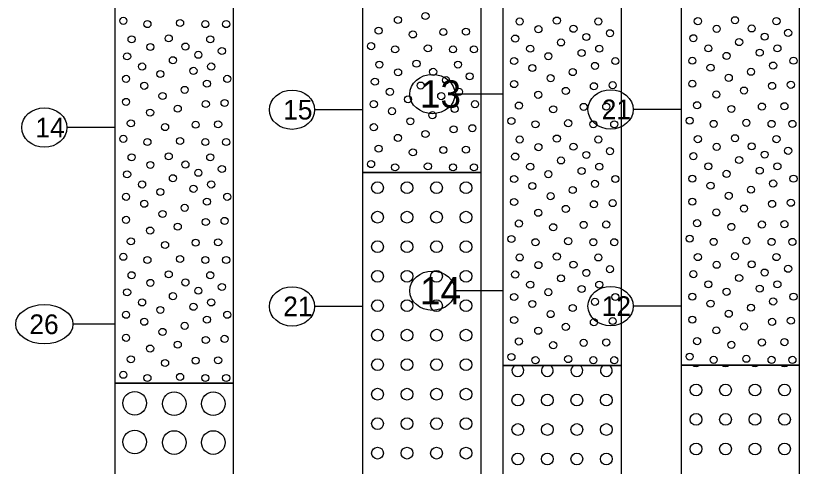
# Model space of a CAD drawing. Extents: x 2345490 to 2436403, y 465165 to 573888.
# Drawn here: x 2389895.3 to 2390094.5, y 557571.2 to 557685.8 of the extents above; entities that cross this region are included whole.
import ezdxf

# ---------------------------------------------------------------- set-up
doc = ezdxf.new("R2010")
doc.units = 0
for name, color, linetype in [('Prop Road Sect_ Boring - Material (Outline)', 7, 'Continuous'), ('Prop Road Sect_ Boring - Peripheral (SPT Oval + Leader)', 7, 'Continuous'), ('Prop Road Sect_ Boring - Peripheral (SPT Tx)', 7, 'Continuous')]:
    doc.layers.add(name, color=color, linetype=linetype)

msp = doc.modelspace()

# ---------------------------------------------------------------- linework, layer by layer
at = {"layer": 'Prop Road Sect_ Boring - Material (Outline)'}
for points in [[(2389983.5425, 557845.85303), (2390013.5425, 557845.85303), (2390013.5425, 557645.85303), (2389983.5425, 557645.85303)], [(2389920.5425, 557842.314), (2389950.5425, 557842.314), (2389950.5425, 557592.314), (2389920.5425, 557592.314)], [(2390019.2285, 557796.83938), (2390049.2285, 557796.83938), (2390049.2285, 557596.83938), (2390019.2285, 557596.83938)], [(2390064.5425, 557696.92666), (2390094.5425, 557696.92666), (2390094.5425, 557596.92666), (2390064.5425, 557596.92666)], [(2389983.5425, 557645.85303), (2390013.5425, 557645.85303), (2390013.5425, 557495.85303), (2389983.5425, 557495.85303)], [(2390019.2285, 557596.83938), (2390049.2285, 557596.83938), (2390049.2285, 557546.83938), (2390019.2285, 557546.83938)], [(2390064.5425, 557596.92666), (2390094.5425, 557596.92666), (2390094.5425, 557496.92666), (2390064.5425, 557496.92666)], [(2389920.5425, 557592.314), (2389950.5425, 557592.314), (2389950.5425, 557492.314), (2389920.5425, 557492.314)]]:
    msp.add_lwpolyline(points, close=True, dxfattribs=at)
for centre, radius in [((2389999.47557, 557685.65437), 0.9), ((2389922.64554, 557684.43532), 0.9), ((2389928.76556, 557683.61032), 0.9), ((2389937.07557, 557683.88032), 0.9), ((2389943.48059, 557683.61032), 0.9), ((2389948.7906, 557683.61032), 0.9), ((2389992.45556, 557684.66437), 0.9), ((2390023.42542, 557684.27036), 0.9), ((2390032.87723, 557684.50221), 0.9), ((2390043.42155, 557684.27036), 0.9), ((2390068.73942, 557684.35764), 0.9), ((2390078.19123, 557684.5895), 0.9), ((2390088.73555, 557684.35764), 0.9), ((2389987.55055, 557681.93436), 0.9), ((2389996.26557, 557680.98936), 0.9), ((2390004.02058, 557681.58936), 0.9), ((2390009.75059, 557681.67936), 0.9), ((2390028.20437, 557682.32105), 0.9), ((2390037.11379, 557682.42714), 0.9), ((2390046.38159, 557681.29574), 0.9), ((2390073.51837, 557682.40833), 0.9), ((2390082.42779, 557682.51443), 0.9), ((2390091.69559, 557681.38303), 0.9), ((2389924.73942, 557679.74498), 0.9), ((2389934.19123, 557679.97684), 0.9), ((2389944.73555, 557679.74498), 0.9), ((2390022.29155, 557679.93074), 0.9), ((2390033.92653, 557678.94902), 0.9), ((2390040.39658, 557680.33574), 0.9), ((2390067.60555, 557680.01803), 0.9), ((2390079.24053, 557679.03631), 0.9), ((2390085.71058, 557680.42303), 0.9), ((2389929.51837, 557677.79567), 0.9), ((2389938.42779, 557677.90177), 0.9), ((2389985.64554, 557678.00435), 0.9), ((2389991.76556, 557677.17935), 0.9), ((2390000.07557, 557677.44935), 0.9), ((2390006.48059, 557677.17935), 0.9), ((2390011.7906, 557677.17935), 0.9), ((2390026.10155, 557677.35074), 0.9), ((2390043.66659, 557677.35074), 0.9), ((2390071.41555, 557677.43802), 0.9), ((2390088.98059, 557677.43802), 0.9), ((2389923.60555, 557675.40537), 0.9), ((2389941.71058, 557675.81037), 0.9), ((2389947.69559, 557676.77037), 0.9), ((2390030.72156, 557675.44573), 0.9), ((2390039.16658, 557676.25573), 0.9), ((2390076.03556, 557675.53302), 0.9), ((2390084.48058, 557676.34302), 0.9), ((2389935.24053, 557674.42365), 0.9), ((2389987.73942, 557673.31401), 0.9), ((2389997.19123, 557673.54587), 0.9), ((2390007.73555, 557673.31401), 0.9), ((2390022.02155, 557674.21573), 0.9), ((2390042.57159, 557672.98573), 0.9), ((2390047.7466, 557674.21573), 0.9), ((2390067.33555, 557674.30301), 0.9), ((2390087.88559, 557673.07301), 0.9), ((2390093.0606, 557674.30301), 0.9), ((2389927.41555, 557672.82536), 0.9), ((2389932.03556, 557670.92036), 0.9), ((2389940.48058, 557671.73036), 0.9), ((2389944.98059, 557672.82536), 0.9), ((2389992.51837, 557671.3647), 0.9), ((2390001.42779, 557671.4708), 0.9), ((2390026.64156, 557672.44573), 0.9), ((2390036.93158, 557671.41072), 0.9), ((2390071.95556, 557672.53301), 0.9), ((2390082.24558, 557671.49801), 0.9), ((2389923.33555, 557669.69035), 0.9), ((2389949.0606, 557669.69035), 0.9), ((2389986.60555, 557668.9744), 0.9), ((2390004.71058, 557669.3794), 0.9), ((2390010.69559, 557670.3394), 0.9), ((2390031.29156, 557669.86572), 0.9), ((2390076.60556, 557669.95301), 0.9), ((2389927.95556, 557667.92035), 0.9), ((2389943.88559, 557668.46035), 0.9), ((2389998.24053, 557667.99268), 0.9), ((2390022.02155, 557668.36572), 0.9), ((2390042.30159, 557667.81072), 0.9), ((2390047.0716, 557668.09572), 0.9), ((2390067.33555, 557668.453), 0.9), ((2390087.61559, 557667.898), 0.9), ((2390092.3856, 557668.183), 0.9), ((2389932.60556, 557665.34035), 0.9), ((2389938.24558, 557666.88535), 0.9), ((2389990.41555, 557666.39439), 0.9), ((2390003.48058, 557665.29939), 0.9), ((2390007.98059, 557666.39439), 0.9), ((2390028.14156, 557665.63571), 0.9), ((2390035.16157, 557666.62571), 0.9), ((2390073.45556, 557665.723), 0.9), ((2390080.47557, 557666.713), 0.9), ((2389923.33555, 557663.84034), 0.9), ((2389943.61559, 557663.28534), 0.9), ((2389948.3856, 557663.57034), 0.9), ((2389986.33555, 557663.25938), 0.9), ((2389995.03556, 557664.48939), 0.9), ((2390012.0606, 557663.25938), 0.9), ((2390068.55055, 557662.99299), 0.9), ((2389929.45556, 557661.11034), 0.9), ((2389936.47557, 557662.10034), 0.9), ((2389990.95556, 557661.48938), 0.9), ((2390006.88559, 557662.02938), 0.9), ((2390023.23655, 557662.90571), 0.9), ((2390031.95157, 557661.9607), 0.9), ((2390039.70658, 557662.56071), 0.9), ((2390045.43659, 557662.65071), 0.9), ((2390077.26557, 557662.04799), 0.9), ((2390085.02058, 557662.64799), 0.9), ((2390090.75059, 557662.73799), 0.9), ((2390001.24558, 557660.45438), 0.9), ((2390021.33154, 557658.9757), 0.9), ((2390066.64554, 557659.06298), 0.9), ((2389924.55055, 557658.38033), 0.9), ((2389933.26557, 557657.43533), 0.9), ((2389941.02058, 557658.03533), 0.9), ((2389946.75059, 557658.12533), 0.9), ((2389986.33555, 557657.40937), 0.9), ((2389995.60556, 557658.90938), 0.9), ((2390011.3856, 557657.13937), 0.9), ((2390027.45156, 557658.1507), 0.9), ((2390035.76157, 557658.4207), 0.9), ((2390042.16659, 557658.1507), 0.9), ((2390047.4766, 557658.1507), 0.9), ((2390072.76556, 557658.23798), 0.9), ((2390081.07557, 557658.50798), 0.9), ((2390087.48059, 557658.23798), 0.9), ((2390092.7906, 557658.23798), 0.9), ((2389999.47557, 557655.66937), 0.9), ((2390006.61559, 557656.85437), 0.9), ((2389922.64554, 557654.45032), 0.9), ((2389928.76556, 557653.62532), 0.9), ((2389937.07557, 557653.89532), 0.9), ((2389943.48059, 557653.62532), 0.9), ((2389948.7906, 557653.62532), 0.9), ((2389992.45556, 557654.67937), 0.9), ((2390023.42542, 557654.28536), 0.9), ((2390032.87723, 557654.51721), 0.9), ((2390043.42155, 557654.28536), 0.9), ((2390068.73942, 557654.37264), 0.9), ((2390078.19123, 557654.6045), 0.9), ((2390088.73555, 557654.37264), 0.9), ((2389987.55055, 557651.94936), 0.9), ((2389996.26557, 557651.00436), 0.9), ((2390004.02058, 557651.60436), 0.9), ((2390009.75059, 557651.69436), 0.9), ((2390028.20437, 557652.33605), 0.9), ((2390037.11379, 557652.44214), 0.9), ((2390046.38159, 557651.31074), 0.9), ((2390073.51837, 557652.42333), 0.9), ((2390082.42779, 557652.52943), 0.9), ((2390091.69559, 557651.39803), 0.9), ((2389924.73942, 557649.75998), 0.9), ((2389934.19123, 557649.99184), 0.9), ((2389944.73555, 557649.75998), 0.9), ((2390022.29155, 557649.94574), 0.9), ((2390040.39658, 557650.35074), 0.9), ((2390067.60555, 557650.03303), 0.9), ((2390079.24053, 557649.05131), 0.9), ((2390085.71058, 557650.43803), 0.9), ((2389929.51837, 557647.81067), 0.9), ((2389938.42779, 557647.91677), 0.9), ((2389985.64554, 557648.01935), 0.9), ((2389991.76556, 557647.19435), 0.9), ((2390000.07557, 557647.46435), 0.9), ((2390006.48059, 557647.19435), 0.9), ((2390011.7906, 557647.19435), 0.9), ((2390026.10155, 557647.36574), 0.9), ((2390033.92653, 557648.96402), 0.9), ((2390043.66659, 557647.36574), 0.9), ((2390071.41555, 557647.45302), 0.9), ((2390088.98059, 557647.45302), 0.9), ((2389923.60555, 557645.42037), 0.9), ((2389941.71058, 557645.82537), 0.9), ((2389947.69559, 557646.78537), 0.9), ((2390030.72156, 557645.46073), 0.9), ((2390039.16658, 557646.27073), 0.9), ((2390076.03556, 557645.54802), 0.9), ((2390084.48058, 557646.35802), 0.9), ((2389935.24053, 557644.43865), 0.9), ((2390022.02155, 557644.23073), 0.9), ((2390047.7466, 557644.23073), 0.9), ((2390067.33555, 557644.31801), 0.9), ((2390087.88559, 557643.08801), 0.9), ((2390093.0606, 557644.31801), 0.9), ((2389927.41555, 557642.84036), 0.9), ((2389940.48058, 557641.74536), 0.9), ((2389944.98059, 557642.84036), 0.9), ((2389987.27939, 557642.0197), 1.5), ((2389994.77939, 557642.0197), 1.5), ((2390002.27939, 557642.0197), 1.5), ((2390009.77939, 557642.0197), 1.5), ((2390026.64156, 557642.46073), 0.9), ((2390036.93158, 557641.42572), 0.9), ((2390042.57159, 557643.00073), 0.9), ((2390071.95556, 557642.54801), 0.9), ((2390082.24558, 557641.51301), 0.9), ((2389923.33555, 557639.70535), 0.9), ((2389932.03556, 557640.93536), 0.9), ((2389949.0606, 557639.70535), 0.9), ((2390031.29156, 557639.88072), 0.9), ((2390076.60556, 557639.96801), 0.9), ((2389927.95556, 557637.93535), 0.9), ((2389943.88559, 557638.47535), 0.9), ((2390022.02155, 557638.38072), 0.9), ((2390042.30159, 557637.82572), 0.9), ((2390047.0716, 557638.11072), 0.9), ((2390067.33555, 557638.468), 0.9), ((2390087.61559, 557637.913), 0.9), ((2390092.3856, 557638.198), 0.9), ((2389932.60556, 557635.35535), 0.9), ((2389938.24558, 557636.90035), 0.9), ((2389987.27939, 557634.5197), 1.5), ((2389994.77939, 557634.5197), 1.5), ((2390002.27939, 557634.5197), 1.5), ((2390009.77939, 557634.5197), 1.5), ((2390028.14156, 557635.65071), 0.9), ((2390035.16157, 557636.64071), 0.9), ((2390073.45556, 557635.738), 0.9), ((2390080.47557, 557636.728), 0.9), ((2389923.33555, 557633.85534), 0.9), ((2389943.61559, 557633.30034), 0.9), ((2389948.3856, 557633.58534), 0.9), ((2389929.45556, 557631.12534), 0.9), ((2389936.47557, 557632.11534), 0.9), ((2390023.23655, 557632.92071), 0.9), ((2390031.95157, 557631.9757), 0.9), ((2390039.70658, 557632.57571), 0.9), ((2390045.43659, 557632.66571), 0.9), ((2390068.55055, 557633.00799), 0.9), ((2390077.26557, 557632.06299), 0.9), ((2390085.02058, 557632.66299), 0.9), ((2390090.75059, 557632.75299), 0.9), ((2390066.64554, 557629.07798), 0.9), ((2389924.55055, 557628.39533), 0.9), ((2389933.26557, 557627.45033), 0.9), ((2389941.02058, 557628.05033), 0.9), ((2389946.75059, 557628.14033), 0.9), ((2389987.27939, 557627.0197), 1.5), ((2389994.77939, 557627.0197), 1.5), ((2390002.27939, 557627.0197), 1.5), ((2390009.77939, 557627.0197), 1.5), ((2390021.33154, 557628.9907), 0.9), ((2390027.45156, 557628.1657), 0.9), ((2390035.76157, 557628.4357), 0.9), ((2390042.16659, 557628.1657), 0.9), ((2390047.4766, 557628.1657), 0.9), ((2390072.76556, 557628.25298), 0.9), ((2390081.07557, 557628.52298), 0.9), ((2390087.48059, 557628.25298), 0.9), ((2390092.7906, 557628.25298), 0.9), ((2389922.64554, 557624.46532), 0.9), ((2389928.76556, 557623.64032), 0.9), ((2389937.07557, 557623.91032), 0.9), ((2389943.48059, 557623.64032), 0.9), ((2389948.7906, 557623.64032), 0.9), ((2390023.42542, 557624.30036), 0.9), ((2390032.87723, 557624.53221), 0.9), ((2390043.42155, 557624.30036), 0.9), ((2390068.73942, 557624.38764), 0.9), ((2390078.19123, 557624.6195), 0.9), ((2390088.73555, 557624.38764), 0.9), ((2390028.20437, 557622.35105), 0.9), ((2390037.11379, 557622.45714), 0.9), ((2390046.38159, 557621.32574), 0.9), ((2390073.51837, 557622.43833), 0.9), ((2390082.42779, 557622.54443), 0.9), ((2390091.69559, 557621.41303), 0.9), ((2389924.73942, 557619.77498), 0.9), ((2389934.19123, 557620.00684), 0.9), ((2389944.73555, 557619.77498), 0.9), ((2389987.27939, 557619.5197), 1.5), ((2389994.77939, 557619.5197), 1.5), ((2390002.27939, 557619.5197), 1.5), ((2390009.77939, 557619.5197), 1.5), ((2390022.29155, 557619.96074), 0.9), ((2390040.39658, 557620.36574), 0.9), ((2390067.60555, 557620.04803), 0.9), ((2390085.71058, 557620.45303), 0.9), ((2389929.51837, 557617.82567), 0.9), ((2389938.42779, 557617.93177), 0.9), ((2390026.10155, 557617.38074), 0.9), ((2390033.92653, 557618.97902), 0.9), ((2390043.66659, 557617.38074), 0.9), ((2390071.41555, 557617.46802), 0.9), ((2390079.24053, 557619.06631), 0.9), ((2390088.98059, 557617.46802), 0.9), ((2389923.60555, 557615.43537), 0.9), ((2389941.71058, 557615.84037), 0.9), ((2389947.69559, 557616.80037), 0.9), ((2390030.72156, 557615.47573), 0.9), ((2390039.16658, 557616.28573), 0.9), ((2390076.03556, 557615.56302), 0.9), ((2390084.48058, 557616.37302), 0.9), ((2389935.24053, 557614.45365), 0.9), ((2390022.02155, 557614.24573), 0.9), ((2390047.7466, 557614.24573), 0.9), ((2390067.33555, 557614.33301), 0.9), ((2390093.0606, 557614.33301), 0.9), ((2389927.41555, 557612.85536), 0.9), ((2389940.48058, 557611.76036), 0.9), ((2389944.98059, 557612.85536), 0.9), ((2389987.27939, 557612.0347), 1.5), ((2389994.77939, 557612.0347), 1.5), ((2390002.27939, 557612.0347), 1.5), ((2390009.77939, 557612.0347), 1.5), ((2390026.64156, 557612.47573), 0.9), ((2390036.93158, 557611.44072), 0.9), ((2390042.57159, 557613.01573), 0.9), ((2390071.95556, 557612.56301), 0.9), ((2390082.24558, 557611.52801), 0.9), ((2390087.88559, 557613.10301), 0.9), ((2389923.33555, 557609.72035), 0.9), ((2389932.03556, 557610.95036), 0.9), ((2389949.0606, 557609.72035), 0.9), ((2390031.29156, 557609.89572), 0.9), ((2390076.60556, 557609.98301), 0.9), ((2389927.95556, 557607.95035), 0.9), ((2389943.88559, 557608.49035), 0.9), ((2390022.02155, 557608.39572), 0.9), ((2390042.30159, 557607.84072), 0.9), ((2390047.0716, 557608.12572), 0.9), ((2390067.33555, 557608.483), 0.9), ((2390087.61559, 557607.928), 0.9), ((2390092.3856, 557608.213), 0.9), ((2389932.60556, 557605.37035), 0.9), ((2389938.24558, 557606.91535), 0.9), ((2390028.14156, 557605.66571), 0.9), ((2390035.16157, 557606.65571), 0.9), ((2390073.45556, 557605.753), 0.9), ((2390080.47557, 557606.743), 0.9), ((2389923.33555, 557603.87034), 0.9), ((2389943.61559, 557603.31534), 0.9), ((2389948.3856, 557603.60034), 0.9), ((2389987.27939, 557604.5347), 1.5), ((2389994.77939, 557604.5347), 1.5), ((2390002.27939, 557604.5347), 1.5), ((2390009.77939, 557604.5347), 1.5), ((2389936.47557, 557602.13034), 0.9), ((2390023.23655, 557602.93571), 0.9), ((2390031.95157, 557601.9907), 0.9), ((2390039.70658, 557602.59071), 0.9), ((2390045.43659, 557602.68071), 0.9), ((2390068.55055, 557603.02299), 0.9), ((2390077.26557, 557602.07799), 0.9), ((2390085.02058, 557602.67799), 0.9), ((2390090.75059, 557602.76799), 0.9), ((2389929.45556, 557601.14034), 0.9), ((2389924.55055, 557598.41033), 0.9), ((2389933.26557, 557597.46533), 0.9), ((2389941.02058, 557598.06533), 0.9), ((2389946.75059, 557598.15533), 0.9), ((2389987.27939, 557597.0347), 1.5), ((2389994.77939, 557597.0347), 1.5), ((2390002.27939, 557597.0347), 1.5), ((2390009.77939, 557597.0347), 1.5), ((2390021.33154, 557599.0057), 0.9), ((2390027.45156, 557598.1807), 0.9), ((2390035.76157, 557598.4507), 0.9), ((2390042.16659, 557598.1807), 0.9), ((2390047.4766, 557598.1807), 0.9), ((2390066.64554, 557599.09298), 0.9), ((2390072.76556, 557598.26798), 0.9), ((2390081.07557, 557598.53798), 0.9), ((2390087.48059, 557598.26798), 0.9), ((2390092.7906, 557598.26798), 0.9), ((2389922.64554, 557594.48032), 0.9), ((2389928.76556, 557593.65532), 0.9), ((2389937.07557, 557593.92532), 0.9), ((2389943.48059, 557593.65532), 0.9), ((2389948.7906, 557593.65532), 0.9), ((2390068.27939, 557590.60833), 1.5), ((2390075.77939, 557590.60833), 1.5), ((2390083.27939, 557590.60833), 1.5), ((2390090.77939, 557590.60833), 1.5), ((2389925.5348, 557587.23829), 3), ((2389935.5848, 557587.11829), 3), ((2389945.5148, 557587.11829), 3), ((2389987.27939, 557589.5347), 1.5), ((2389994.77939, 557589.5347), 1.5), ((2390002.27939, 557589.5347), 1.5), ((2390009.77939, 557589.5347), 1.5), ((2390022.96539, 557588.05104), 1.5), ((2390030.46539, 557588.05104), 1.5), ((2390037.96539, 557588.05104), 1.5), ((2390045.46539, 557588.05104), 1.5), ((2390068.27939, 557583.12333), 1.5), ((2390075.77939, 557583.12333), 1.5), ((2390083.27939, 557583.12333), 1.5), ((2390090.77939, 557583.12333), 1.5), ((2389987.27939, 557582.0497), 1.5), ((2389994.77939, 557582.0497), 1.5), ((2390002.27939, 557582.0497), 1.5), ((2390009.77939, 557582.0497), 1.5), ((2389925.5348, 557577.39829), 3), ((2389935.5848, 557577.24829), 3), ((2389945.5148, 557577.24829), 3), ((2390022.96539, 557580.55104), 1.5), ((2390030.46539, 557580.55104), 1.5), ((2390037.96539, 557580.55104), 1.5), ((2390045.46539, 557580.55104), 1.5), ((2390068.27939, 557575.62333), 1.5), ((2390075.77939, 557575.62333), 1.5), ((2390083.27939, 557575.62333), 1.5), ((2390090.77939, 557575.62333), 1.5), ((2389987.27939, 557574.5497), 1.5), ((2389994.77939, 557574.5497), 1.5), ((2390002.27939, 557574.5497), 1.5), ((2390009.77939, 557574.5497), 1.5), ((2390022.96539, 557573.06604), 1.5), ((2390030.46539, 557573.06604), 1.5), ((2390037.96539, 557573.06604), 1.5), ((2390045.46539, 557573.06604), 1.5)]:
    msp.add_circle(centre, radius, dxfattribs=at)
for centre, start, end in [((2390022.96539, 557595.55104), 120.8079446, 59.1920554), ((2390030.46539, 557595.55104), 120.8079446, 59.1920554), ((2390037.96539, 557595.55104), 120.8079446, 59.1920554), ((2390045.46539, 557595.55104), 120.8079446, 59.1920554), ((2390068.27939, 557598.10833), 231.9783236, 308.0216764), ((2390075.77939, 557598.10833), 231.9783236, 308.0216764), ((2390083.27939, 557598.10833), 231.9783236, 308.0216764), ((2390090.77939, 557598.10833), 231.9783236, 308.0216764)]:
    msp.add_arc(centre, 1.5, start, end, dxfattribs=at)
at = {"layer": 'Prop Road Sect_ Boring - Peripheral (SPT Oval + Leader)'}
for p, q in [((2390019.2285, 557665.83938), (2390006.97259, 557665.83938)), ((2389983.5425, 557661.85303), (2389971.28659, 557661.85303)), ((2390064.5425, 557661.92666), (2390052.28659, 557661.92666)), ((2389920.5425, 557657.314), (2389908.28659, 557657.314)), ((2390019.2285, 557615.83938), (2390006.97259, 557615.83938)), ((2389983.5425, 557611.85303), (2389971.28659, 557611.85303)), ((2390064.5425, 557611.92666), (2390052.28659, 557611.92666)), ((2389920.5425, 557607.314), (2389909.82203, 557607.314))]:
    msp.add_line(p, q, dxfattribs=at)
for centre, major_axis, ratio in [((2390001.2285, 557665.83938), (5.74409, 0), 0.870459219), ((2389965.5425, 557661.85303), (5.74409, 0), 0.870459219), ((2390046.5425, 557661.92666), (5.74409, 0), 0.870459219), ((2389902.5425, 557657.314), (5.74409, 0), 0.870459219), ((2390001.2285, 557615.83938), (5.74409, 0), 0.870459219), ((2389965.5425, 557611.85303), (5.74409, 0), 0.870459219), ((2390046.5425, 557611.92666), (5.74409, 0), 0.870459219), ((2389902.5425, 557607.314), (7.27953, 0), 0.686857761)]:
    msp.add_ellipse(centre, major_axis=major_axis, ratio=ratio, dxfattribs=at)

# ---------------------------------------------------------------- texts
at = {"layer": 'Prop Road Sect_ Boring - Peripheral (SPT Tx)'}
for s, height, p in [('13', 7, (2389998.08677, 557662.33938)), ('15', 5, (2389963.29841, 557659.35303)), ('21', 5, (2390044.29841, 557659.42666)), ('14', 5, (2389900.29841, 557654.814)), ('14', 7, (2389998.08677, 557612.33938)), ('21', 5, (2389963.29841, 557609.35303)), ('12', 5, (2390044.29841, 557609.42666)), ('26', 5, (2389898.76297, 557604.814))]:
    msp.add_text(s, height=height, dxfattribs=at).set_placement(p)

doc.saveas('drawing.dxf')
